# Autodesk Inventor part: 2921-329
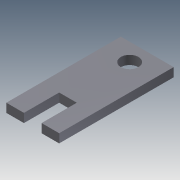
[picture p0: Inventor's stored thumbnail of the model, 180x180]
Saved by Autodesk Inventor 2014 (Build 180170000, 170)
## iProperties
Company: NHTSA/VRTC
Created: 2012-08
Part Number: 2921-329
Material: Steel, Mild
Document SubType Name: Modeling
Designer: Mike Vanvoorhis
Density: 7.86 g/cm^3
Mass: 134.555 g
Surface Area: 74.9998 cm^2
Volume: 17.119 cm^3
Project: CHILD SIDE IMPACT SLED
Description: D-RING LOWER ANCHOR PLATE
Stock Number: BAR 1.5" (3.81mm) x 1/4" (6.35mm) X 3.25" (82.6mm)
Appearance: Steel
DESIGN DATE: 2012-11-05
Author: Dave Walker
Title: D-Ring Lower Anchor Plate
Subject: Child SIde Impact Sled
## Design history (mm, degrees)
sketch "Sketch1"
  geometry: L1 (0, 0)-(38.1, 0); L2 (38.1, 0)-(38.1, 6.35); L3 (38.1, 6.35)-(0, 6.35); L4 (0, 6.35)-(0, 0)
  constraints: 8 end point, 2 parallel, 1 horizontal, 1 perpendicular
  dimensions: "d0" = 38.1 distance of L3.end L2.end; "d1" = 6.35 distance of L2.end L1.end
extrude "Extrusion1" new body sketch "Sketch1" distance "d2" = 82.55; taper "d3" = 0 deg
sketch "Sketch2"
  geometry: L1 (38.1, 82.55)-(0, 82.55) reference; L2 (38.1, 0)-(0, 0) reference; L3 (25.4, 25.4)-(25.4, 0); L4 (12.7, 25.4)-(12.7, 0); L5 (12.7, 25.4)-(25.4, 25.4); L6 (19.05, 82.55)-(19.05, 69.85)
  constraints: 8 end point, 4 perpendicular, 2 point on line, 1 midpoint
  dimensions: "d7" = 12.7 distance of L6.start L6.end
hole "Hole1" sketch "Sketch2" at (19.05, 69.85) diameter "d8" = 12.7; stored, may be unused: countersink angle "d12" = 82 deg, drill point angle "d14" = 118 deg; dims "d9" = 19.05, "d10" = 9.525, "d11" = 6.35, "d13" = 25.4
sketch "Sketch3"
  geometry: L1 (38.1, 0)-(0, 0) reference; L2 (12.7, 25.4)-(12.7, 0); L3 (25.4, 0)-(25.4, 25.4); L4 (25.4, 25.4)-(12.7, 25.4)
  constraints: 6 end point, 2 point on line, 1 parallel, 1 perpendicular
extrude "Extrusion2" cut sketch "Sketch3" distance "d18" = 6.35; taper "d19" = 0 deg
body "Solid1"
